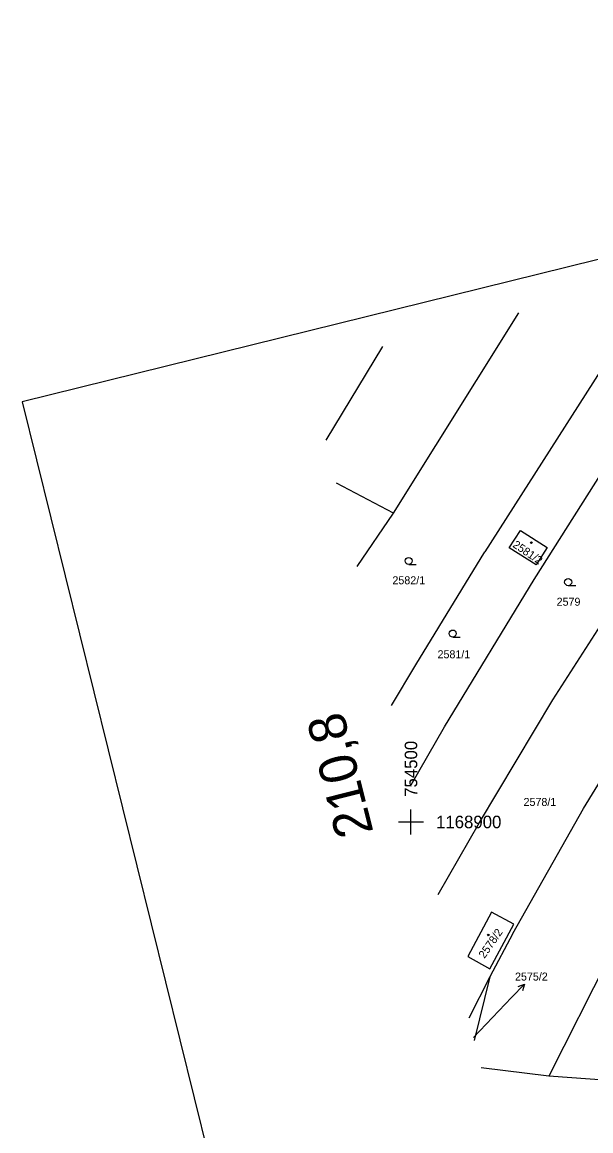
# Model space of a CAD drawing. Extents: x -754679 to -754173, y -1169241 to -1168288.
# Drawn here: x -754562 to -754471.3, y -1168949.2 to -1168772.6 of the extents above; entities that cross this region are included whole.
import ezdxf

# ---------------------------------------------------------------- set-up
doc = ezdxf.new("R2010")
doc.units = 0
for name, color, linetype in [('Default', 7, 'Continuous'), ('Vrstva 1', 7, 'Continuous'), ('Vrstva 16', 7, 'Continuous'), ('Vrstva 18', 7, 'Continuous'), ('Vrstva 19', 7, 'Continuous'), ('Vrstva 25', 7, 'Continuous'), ('Vrstva 61', 7, 'Continuous'), ('Vrstva 7', 7, 'Continuous')]:
    doc.layers.add(name, color=color, linetype=linetype)

msp = doc.modelspace()

# ---------------------------------------------------------------- linework, layer by layer
at = {"layer": 'Default'}
for points in [[(-754500, -1168902), (-754500, -1168900), (-754500, -1168898)], [(-754502, -1168900), (-754500, -1168900), (-754498, -1168900)]]:
    msp.add_lwpolyline(points, dxfattribs=at)
at = {"layer": 'Vrstva 1'}
for p, q in [((-754460.34, -1168813.33), (-754488.24, -1168856.95)), ((-754502.8, -1168850.81), (-754482.79, -1168818.88)), ((-754504.55, -1168824.26), (-754513.55, -1168839.17)), ((-754477.37, -1168880.54), (-754443.28, -1168827.28)), ((-754480.34, -1168861.35), (-754467.51, -1168841.1)), ((-754502.8, -1168850.81), (-754511.86, -1168846.04)), ((-754508.58, -1168859.28), (-754502.8, -1168850.81)), ((-754484.32, -1168856.31), (-754482.56, -1168853.56)), ((-754482.56, -1168853.56), (-754478.3, -1168856.26)), ((-754480.05, -1168859.02), (-754484.32, -1168856.31)), ((-754478.3, -1168856.26), (-754480.05, -1168859.02)), ((-754499.2, -1168874.96), (-754488.24, -1168856.95)), ((-754494.64, -1168884.83), (-754480.34, -1168861.35)), ((-754503.1, -1168881.46), (-754499.2, -1168874.96)), ((-754472.47, -1168897.88), (-754460.56, -1168878.23)), ((-754489.07, -1168900.09), (-754477.37, -1168880.54)), ((-754499.98, -1168894.07), (-754494.64, -1168884.83)), ((-754483.78, -1168917.79), (-754472.47, -1168897.88)), ((-754495.66, -1168911.55), (-754489.07, -1168900.09)), ((-754487.14, -1168914.36), (-754490.93, -1168921.44)), ((-754483.59, -1168916.28), (-754487.14, -1168914.36)), ((-754487.4, -1168923.38), (-754483.59, -1168916.28)), ((-754483.78, -1168917.79), (-754487.43, -1168924.67)), ((-754490.93, -1168921.44), (-754487.4, -1168923.38)), ((-754468.49, -1168921.69), (-754478.02, -1168940.49)), ((-754487.43, -1168924.67), (-754490.78, -1168931.27)), ((-754487.43, -1168924.67), (-754489.9, -1168934.81)), ((-754478.02, -1168940.49), (-754488.82, -1168939.18)), ((-754468.53, -1168941.18), (-754478.02, -1168940.49))]:
    msp.add_line(p, q, dxfattribs=at)
at = {"layer": 'Vrstva 16'}
for p in [(-754481.88, -1168925.82), (-754490.02, -1168934.35)]:
    msp.add_line(p, (-754483.95, -1168927.99), dxfattribs=at)
msp.add_lwpolyline([(-754482.93, -1168926.2), (-754481.88, -1168925.82), (-754482.21, -1168926.89)], dxfattribs=at)
at = {"layer": 'Vrstva 25'}
for p, q in [((-754500.36, -1168858.97), (-754499.16, -1168858.97)), ((-754474.94, -1168862.35), (-754473.74, -1168862.35)), ((-754493.34, -1168870.54), (-754492.14, -1168870.54))]:
    msp.add_line(p, q, dxfattribs=at)
for centre, radius in [((-754480.81, -1168855.5), 0.131), ((-754500.36, -1168858.41), 0.562), ((-754474.94, -1168861.79), 0.562), ((-754493.34, -1168869.98), 0.562), ((-754487.67, -1168918), 0.131)]:
    msp.add_circle(centre, radius, dxfattribs=at)
at = {"layer": 'Vrstva 61'}
msp.add_line((-754561.97, -1168833.08), (-754461.15, -1169240.8), dxfattribs=at)
msp.add_lwpolyline([(-754461.15, -1169240.8), (-754172.83, -1169169.5), (-754273.65, -1168761.78), (-754561.97, -1168833.08)], dxfattribs=at)

# ---------------------------------------------------------------- texts
at = {"layer": 'Default'}
msp.add_text('754500', height=2, rotation=90, dxfattribs=at).set_placement((-754499, -1168896))
msp.add_text('1168900', height=2, dxfattribs=at).set_placement((-754496, -1168901))
at = {"layer": 'Vrstva 16'}
msp.add_text('2575/2', height=1.275, rotation=360, dxfattribs=at).set_placement((-754483.41, -1168925.27))
at = {"layer": 'Vrstva 18'}
for s, p in [('2582/1', (-754502.95, -1168862.13)), ('2579', (-754476.78, -1168865.55)), ('2581/1', (-754495.76, -1168873.92)), ('2578/1', (-754482.05, -1168897.45))]:
    msp.add_text(s, height=1.275, rotation=360, dxfattribs=at).set_placement(p)
at = {"layer": 'Vrstva 19'}
for s, rotation, p in [('2581/2', 325.8984, (-754483.89, -1168856.11)), ('2578/2', 55.2904, (-754488.27, -1168921.84))]:
    msp.add_text(s, height=1.275, rotation=rotation, dxfattribs=at).set_placement(p)
at = {"layer": 'Vrstva 7'}
msp.add_text('210,8', height=6, rotation=104.1786, dxfattribs=at).set_placement((-754505.95, -1168901.61))

doc.saveas('drawing.dxf')
